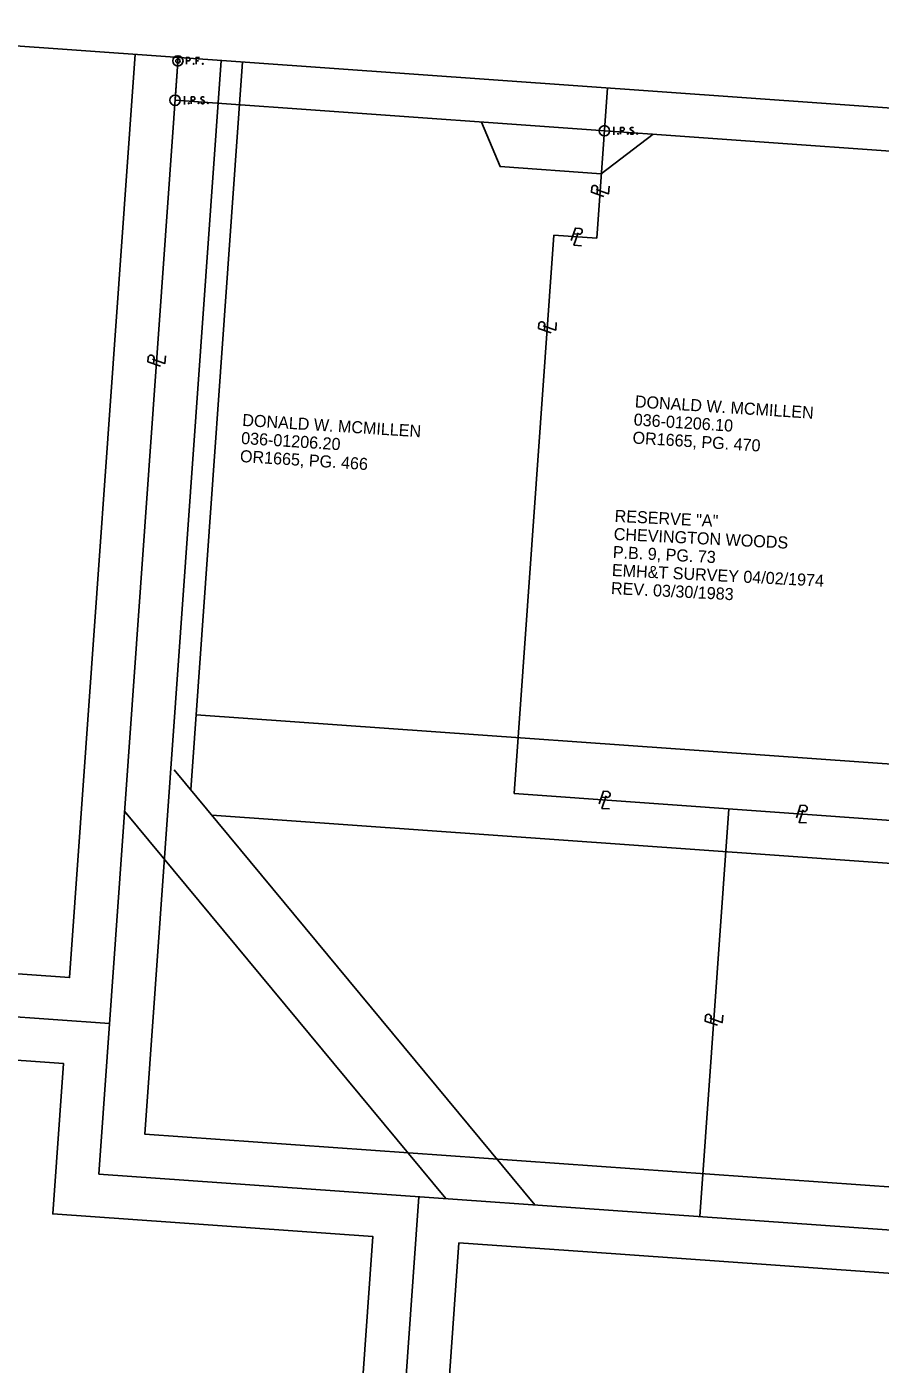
# Model space of a CAD drawing. Extents: x 1898254 to 1901377, y 701554 to 704886.
# Drawn here: x 1899449.8 to 1899648.1, y 702919.7 to 703230.4 of the extents above; entities that cross this region are included whole.
import ezdxf

# ---------------------------------------------------------------- set-up
doc = ezdxf.new("R2010")
doc.units = 0
for name, color, linetype in [('_CIVIL_CONSTRUCTION', 7, 'Continuous'), ('DV_X_Property_Line', 7, 'Continuous'), ('DV_X_Text', 7, 'Continuous'), ('PF_X_Ground_Line', 7, 'Continuous'), ('RW_X_Esmt_General', 7, 'Continuous'), ('RW_X_Esmt_SW', 7, 'Continuous'), ('RW_X_Esmt_U', 7, 'Continuous'), ('RW_X_Fee_RW', 7, 'Continuous'), ('SC_Scratch2', 7, 'Continuous'), ('SC_Scratch5', 7, 'Continuous'), ('SG_X_Manhole', 7, 'Continuous'), ('SV_P_Mon_Cells_Set', 7, 'Continuous'), ('SV_X_Mon_Cells_Found', 7, 'Continuous')]:
    doc.layers.add(name, color=color, linetype=linetype)

msp = doc.modelspace()

# ---------------------------------------------------------------- linework, layer by layer
at = {"layer": '_CIVIL_CONSTRUCTION'}
msp.add_lwpolyline([(1899555.47, 703208.25), (1899559.75, 703197.92), (1899583.29, 703196.24), (1899595.37, 703205.41)], dxfattribs=at)
at = {"layer": 'DV_X_Property_Line'}
for p, q in [((1899466.52, 702963.89), (1899484.96, 703223.29)), ((1899582.23, 703181.28), (1899584.71, 703216.19)), ((1899582.33, 703191.5), (1899582.42, 703192.8)), ((1899583.01, 703192.26), (1899583.01, 703192.26)), ((1899563.03, 703052.28), (1899572.25, 703181.99)), ((1899582.23, 703181.28), (1899572.25, 703181.99)), ((1899576.83, 703182.29), (1899578.12, 703182.2)), ((1899577.58, 703181.61), (1899577.58, 703181.61)), ((1899570.06, 703159.86), (1899570.15, 703161.15)), ((1899570.73, 703160.62), (1899570.73, 703160.62)), ((1899479.28, 703152.1), (1899479.37, 703153.39)), ((1899479.96, 703152.86), (1899479.96, 703152.86)), ((1899469, 702998.85), (1898413.79, 703073.89)), ((1899652.8, 703045.9), (1899563.03, 703052.28)), ((1899583.32, 703051.46), (1899584.62, 703051.37)), ((1899584.08, 703050.79), (1899584.08, 703050.79)), ((1899606.17, 702954), (1899612.91, 703048.74)), ((1899629.13, 703048.21), (1899630.43, 703048.11)), ((1899629.89, 703047.53), (1899629.89, 703047.53)), ((1899608.74, 702998.98), (1899608.83, 703000.27)), ((1899609.42, 702999.73), (1899609.42, 702999.73)), ((1899466.52, 702963.89), (1899765.35, 702942.72)), ((1899476.33, 702046.99), (1899540.91, 702958.62))]:
    msp.add_line(p, q, dxfattribs=at)
for points in [[(1899583.89, 703190.97), (1899580.99, 703191.96), (1899581.06, 703192.99)], [(1899582.07, 703192.59), (1899584.96, 703191.59), (1899585.09, 703193.34)], [(1899576.29, 703180.73), (1899577.28, 703183.64), (1899578.31, 703183.56)], [(1899577.91, 703182.55), (1899576.92, 703179.66), (1899578.66, 703179.53)], [(1899571.61, 703159.33), (1899568.71, 703160.32), (1899568.79, 703161.35)], [(1899569.8, 703160.95), (1899572.69, 703159.95), (1899572.81, 703161.69)], [(1899480.83, 703151.57), (1899477.93, 703152.56), (1899478.01, 703153.59)], [(1899479.02, 703153.19), (1899481.91, 703152.19), (1899482.03, 703153.93)], [(1899582.79, 703049.91), (1899583.78, 703052.81), (1899584.81, 703052.73)], [(1899584.41, 703051.72), (1899583.41, 703048.83), (1899585.16, 703048.71)], [(1899628.6, 703046.65), (1899629.59, 703049.55), (1899630.62, 703049.48)], [(1899630.22, 703048.47), (1899629.22, 703045.57), (1899630.96, 703045.45)], [(1899610.3, 702998.45), (1899607.4, 702999.44), (1899607.47, 703000.47)], [(1899608.48, 703000.07), (1899611.37, 702999.07), (1899611.5, 703000.81)]]:
    msp.add_lwpolyline(points, dxfattribs=at)
for centre, start, end in [((1899581.73, 703192.84), 356.4035, 167.2606), ((1899578.16, 703182.89), 266.4035, 77.2606), ((1899569.46, 703161.2), 356.4035, 167.2606), ((1899478.68, 703153.44), 356.4035, 167.2606), ((1899584.66, 703052.06), 266.4035, 77.2606), ((1899630.47, 703048.8), 266.4035, 77.2606), ((1899608.15, 703000.31), 356.4035, 167.2606)]:
    msp.add_arc(centre, 0.69, start, end, dxfattribs=at)
at = {"layer": 'PF_X_Ground_Line'}
msp.add_lwpolyline([(1899484.96, 703223.29), (1899484.25, 703213.31), (1899745, 703194.77), (1899766.64, 703173.17), (1899778.77, 703132.21)], dxfattribs=at)
at = {"layer": 'RW_X_Esmt_General'}
msp.add_line((1899550.18, 702947.94), (1899541.7, 702828.32), dxfattribs=at)
at = {"layer": 'RW_X_Esmt_SW'}
for p, q in [((1899487.9, 703053.14), (1899499.93, 703222.22)), ((1899489.14, 703070.57), (1899772.98, 703050.39)), ((1899484.06, 703057.77), (1899567.87, 702956.71)), ((1899472.51, 703048.2), (1899547.17, 702958.18)), ((1899492.79, 703047.25), (1899771.35, 703027.44))]:
    msp.add_line(p, q, dxfattribs=at)
at = {"layer": 'RW_X_Esmt_U'}
for points in [[(1899327.17, 703234.74), (1899312.22, 703020.03), (1899459.74, 703009.54), (1899474.99, 703224)], [(1899494.94, 703222.58), (1899477.2, 702973.16), (1899766.06, 702952.7)], [(1898413.09, 703063.91), (1899458.32, 702989.59), (1899455.83, 702954.62), (1899530.23, 702949.35), (1899466.62, 702051.43)], [(1899550.18, 702947.94), (1899580.04, 702945.82), (1899764.64, 702932.75)]]:
    msp.add_lwpolyline(points, dxfattribs=at)
at = {"layer": 'RW_X_Fee_RW'}
msp.add_line((1898449.4, 703296.93), (1899763.77, 703203.46), dxfattribs=at)
at = {"layer": 'SC_Scratch2'}
msp.add_circle((1899815.76, 703229.84), 1561.35, dxfattribs=at)
at = {"layer": 'SC_Scratch5'}
msp.add_line((1898449.4, 703296.93), (1899763.77, 703203.46), dxfattribs=at)
for points in [[(1899484.96, 703223.29), (1899484.25, 703213.31), (1899745, 703194.77), (1899780.89, 703162.13)], [(1899555.47, 703208.25), (1899559.75, 703197.92), (1899583.29, 703196.24), (1899595.37, 703205.41)]]:
    msp.add_lwpolyline(points, dxfattribs=at)
at = {"layer": 'SG_X_Manhole'}
for points in [[(1899484.96, 703223.29), (1899484.25, 703213.31), (1899745, 703194.77), (1899780.89, 703162.13)], [(1899484.96, 703223.29), (1899484.25, 703213.31), (1899745, 703194.77), (1899745, 703194.77)]]:
    msp.add_lwpolyline(points, dxfattribs=at)
at = {"layer": 'SV_P_Mon_Cells_Set'}
for points in [[(1899486.27, 703214.11), (1899486.63, 703214.11)], [(1899486.45, 703212.51), (1899486.45, 703214.11)], [(1899488.02, 703212.51), (1899488.02, 703214.11), (1899488.54, 703214.11), (1899488.6, 703214.1), (1899488.68, 703214.08), (1899488.71, 703214.05), (1899488.74, 703214.03), (1899488.79, 703213.96), (1899488.82, 703213.9), (1899488.84, 703213.8), (1899488.84, 703213.65), (1899488.83, 703213.6), (1899488.81, 703213.52), (1899488.76, 703213.43), (1899488.72, 703213.4), (1899488.69, 703213.37), (1899488.63, 703213.34), (1899488.54, 703213.33), (1899488.02, 703213.33)], [(1899491.02, 703214), (1899491, 703214.03), (1899490.97, 703214.05), (1899490.87, 703214.09), (1899490.75, 703214.11), (1899490.66, 703214.11), (1899490.63, 703214.11), (1899490.48, 703214.08), (1899490.36, 703214), (1899490.29, 703213.9), (1899490.26, 703213.8), (1899490.26, 703213.72), (1899490.29, 703213.62), (1899490.37, 703213.53), (1899490.98, 703213.16), (1899491.04, 703213.11), (1899491.06, 703213.06), (1899491.08, 703212.98), (1899491.08, 703212.9), (1899491.07, 703212.83), (1899491.06, 703212.78), (1899491.04, 703212.72), (1899491.01, 703212.66), (1899490.99, 703212.63), (1899490.96, 703212.59), (1899490.93, 703212.56), (1899490.88, 703212.54), (1899490.85, 703212.53), (1899490.75, 703212.51), (1899490.59, 703212.51), (1899490.5, 703212.54), (1899490.35, 703212.63), (1899490.26, 703212.7)], [(1899486.27, 703212.51), (1899486.63, 703212.51)], [(1899487.41, 703212.73), (1899487.46, 703212.73), (1899487.5, 703212.7), (1899487.53, 703212.65), (1899487.53, 703212.59), (1899487.5, 703212.54), (1899487.46, 703212.51), (1899487.41, 703212.51), (1899487.38, 703212.54), (1899487.34, 703212.59), (1899487.34, 703212.65), (1899487.38, 703212.7), (1899487.41, 703212.73)], [(1899489.66, 703212.73), (1899489.71, 703212.73), (1899489.75, 703212.7), (1899489.78, 703212.65), (1899489.78, 703212.59), (1899489.75, 703212.54), (1899489.71, 703212.51), (1899489.66, 703212.51), (1899489.62, 703212.54), (1899489.59, 703212.59), (1899489.59, 703212.65), (1899489.62, 703212.7), (1899489.66, 703212.73)], [(1899491.84, 703212.73), (1899491.9, 703212.73), (1899491.93, 703212.7), (1899491.96, 703212.65), (1899491.96, 703212.59), (1899491.93, 703212.54), (1899491.9, 703212.51), (1899491.84, 703212.51), (1899491.81, 703212.54), (1899491.77, 703212.59), (1899491.77, 703212.65), (1899491.81, 703212.7), (1899491.84, 703212.73)], [(1899586.02, 703207.02), (1899586.37, 703207.02)], [(1899586.02, 703205.42), (1899586.37, 703205.42)], [(1899586.2, 703205.42), (1899586.2, 703207.02)], [(1899587.16, 703205.63), (1899587.21, 703205.63), (1899587.25, 703205.61), (1899587.28, 703205.56), (1899587.28, 703205.5), (1899587.25, 703205.45), (1899587.21, 703205.42), (1899587.16, 703205.42), (1899587.12, 703205.45), (1899587.09, 703205.5), (1899587.09, 703205.56), (1899587.12, 703205.61), (1899587.16, 703205.63)], [(1899587.76, 703205.42), (1899587.76, 703207.02), (1899588.29, 703207.02), (1899588.35, 703207.01), (1899588.42, 703206.98), (1899588.46, 703206.96), (1899588.49, 703206.93), (1899588.53, 703206.87), (1899588.57, 703206.81), (1899588.59, 703206.71), (1899588.59, 703206.55), (1899588.58, 703206.5), (1899588.56, 703206.43), (1899588.51, 703206.34), (1899588.47, 703206.3), (1899588.44, 703206.28), (1899588.38, 703206.25), (1899588.29, 703206.24), (1899587.76, 703206.24)], [(1899589.41, 703205.63), (1899589.46, 703205.63), (1899589.49, 703205.61), (1899589.53, 703205.56), (1899589.53, 703205.5), (1899589.49, 703205.45), (1899589.46, 703205.42), (1899589.41, 703205.42), (1899589.37, 703205.45), (1899589.34, 703205.5), (1899589.34, 703205.56), (1899589.37, 703205.61), (1899589.41, 703205.63)], [(1899590.77, 703206.91), (1899590.75, 703206.93), (1899590.72, 703206.96), (1899590.62, 703207), (1899590.5, 703207.02), (1899590.41, 703207.02), (1899590.38, 703207.02), (1899590.23, 703206.98), (1899590.11, 703206.91), (1899590.03, 703206.81), (1899590.01, 703206.71), (1899590.01, 703206.63), (1899590.03, 703206.53), (1899590.12, 703206.44), (1899590.73, 703206.06), (1899590.78, 703206.01), (1899590.81, 703205.96), (1899590.83, 703205.89), (1899590.83, 703205.81), (1899590.82, 703205.74), (1899590.81, 703205.68), (1899590.78, 703205.62), (1899590.76, 703205.57), (1899590.74, 703205.53), (1899590.71, 703205.5), (1899590.67, 703205.47), (1899590.63, 703205.45), (1899590.6, 703205.43), (1899590.5, 703205.42), (1899590.34, 703205.42), (1899590.24, 703205.45), (1899590.1, 703205.53), (1899590.01, 703205.61)], [(1899591.59, 703205.63), (1899591.64, 703205.63), (1899591.68, 703205.61), (1899591.71, 703205.56), (1899591.71, 703205.5), (1899591.68, 703205.45), (1899591.64, 703205.42), (1899591.59, 703205.42), (1899591.56, 703205.45), (1899591.52, 703205.5), (1899591.52, 703205.56), (1899591.56, 703205.61), (1899591.59, 703205.63)]]:
    msp.add_lwpolyline(points, dxfattribs=at)
for centre in [(1899484.25, 703213.31), (1899584, 703206.22)]:
    msp.add_circle(centre, 1.2, dxfattribs=at)
at = {"layer": 'SV_X_Mon_Cells_Found'}
for points in [[(1899486.9, 703221.67), (1899486.9, 703223.27), (1899487.43, 703223.27), (1899487.49, 703223.25), (1899487.56, 703223.23), (1899487.6, 703223.2), (1899487.63, 703223.18), (1899487.67, 703223.11), (1899487.71, 703223.05), (1899487.73, 703222.95), (1899487.73, 703222.8), (1899487.72, 703222.75), (1899487.7, 703222.67), (1899487.65, 703222.59), (1899487.61, 703222.55), (1899487.58, 703222.52), (1899487.52, 703222.5), (1899487.43, 703222.49), (1899486.9, 703222.49)], [(1899489.91, 703223.27), (1899489.15, 703223.27), (1899489.15, 703221.67)], [(1899488.55, 703221.88), (1899488.6, 703221.88), (1899488.63, 703221.86), (1899488.67, 703221.8), (1899488.67, 703221.74), (1899488.63, 703221.69), (1899488.6, 703221.67), (1899488.55, 703221.67), (1899488.51, 703221.69), (1899488.48, 703221.74), (1899488.48, 703221.8), (1899488.51, 703221.86), (1899488.55, 703221.88)], [(1899489.15, 703222.49), (1899489.69, 703222.49)], [(1899490.69, 703221.88), (1899490.75, 703221.88), (1899490.78, 703221.86), (1899490.82, 703221.8), (1899490.82, 703221.74), (1899490.78, 703221.69), (1899490.75, 703221.67), (1899490.69, 703221.67), (1899490.66, 703221.69), (1899490.63, 703221.74), (1899490.63, 703221.8), (1899490.66, 703221.86), (1899490.69, 703221.88)]]:
    msp.add_lwpolyline(points, dxfattribs=at)
for radius in [1.2, 0.495]:
    msp.add_circle((1899484.91, 703222.47), radius, dxfattribs=at)

# ---------------------------------------------------------------- texts
at = {"layer": 'DV_X_Text'}
for s, rotation, p in [('DONALD W. MCMILLEN', 356.3351, (1899591.02, 703141.99)), ('DONALD W. MCMILLEN', 356.3351, (1899499.81, 703137.68)), ('036-01206.10', 356.3351, (1899590.75, 703137.79)), ('036-01206.20', 356.3351, (1899499.54, 703133.49)), ('OR1665, PG. 470', 356.3351, (1899590.48, 703133.6)), ('OR1665, PG. 466', 356.3351, (1899499.27, 703129.3)), ('RESERVE "A"', 357.0949, (1899586.33, 703115.4)), ('CHEVINGTON WOODS', 357.0949, (1899586.12, 703111.21)), ('P.B. 9, PG. 73', 357.0949, (1899585.91, 703107.01)), ('EMH&T SURVEY 04/02/1974', 357.0949, (1899585.69, 703102.82)), ('REV. 03/30/1983', 357.0949, (1899585.48, 703098.62))]:
    msp.add_text(s, height=2.8, rotation=rotation, dxfattribs=at).set_placement(p)

doc.saveas('drawing.dxf')
